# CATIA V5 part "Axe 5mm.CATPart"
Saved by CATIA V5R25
Part number: Axe 5mm
Bounding box of the stored display mesh (mm): x -55 to 55, y -2.5 to 2.5, z -2.486 to 2.486
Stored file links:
  C:\Users\m000605\Desktop\Projet FAB liseuse\Axe 5mm.CATPart
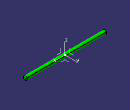
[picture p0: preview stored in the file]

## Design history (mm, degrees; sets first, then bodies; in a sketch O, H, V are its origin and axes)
AxisSystem1: origin (0, 0, 0), X (1, 0, 0), Y (0, 1, 0), Z (0, 0, 1)
Set1
  Sketch1 on XY plane of AxisSystem1, origin (0, 0, 0), H (1, 0, 0), V (0, 1, 0)
    axis line L1 (-141.5651, 0) -> (117.6225, 0)
    point P1 (-141.5651, 0)
    line L2 (-55, 0) -> (-55, 2.5)
    point P3 (-55, 0)
    line L3 (-55, 2.5) -> (55, 2.5)
    line L4 (55, 2.5) -> (55, 0)
    point P6 (55, 0)
    reference intersected line E1 through (0, 0) direction (0, 1) from YZ plane of AxisSystem1
    distance L1 L3 = 2.5
    length L3 = 110
    coincidence: P1 H, P3 L1, P6 L1
    horizontal: L1 H, L3 H
    vertical: L2 V, L4 V
    symmetry: L2 L4 E1
Body1 (main body)
  Shaft1: profile Sketch1, axis Sketch1.L1, angle 360
  Chamfer1: length 1, angle 45, on edge [face of Shaft1 from Sketch1.L3 | face of Shaft1 from Sketch1.L4]; edge [face of Shaft1 from Sketch1.L2 | face of Shaft1 from Sketch1.L3]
